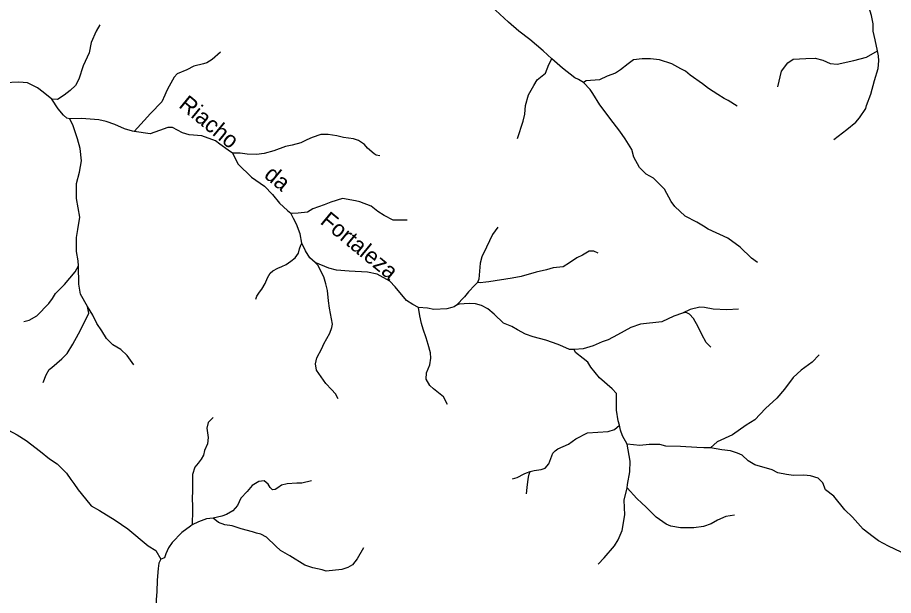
# Model space of a CAD drawing. Extents: x 717.8 to 772.7, y 8672.2 to 8728.
# Drawn here: x 745.36 to 756.1, y 8714.76 to 8721.84 of the extents above; entities that cross this region are included whole.
import ezdxf
from ezdxf.enums import TextEntityAlignment as Align

# ---------------------------------------------------------------- set-up
doc = ezdxf.new("R2010")
doc.units = 0
doc.header["$LTSCALE"] = 0.08
doc.linetypes.add('LONG_DASHED', pattern=[7.5, 6, -1.5])
doc.layers.add('61', color=7, linetype='Continuous')
doc.layers.add('9', color=7, linetype='LONG_DASHED', lineweight=25)

msp = doc.modelspace()

# ---------------------------------------------------------------- linework, layer by layer
at = {"layer": '9'}
for points in [[(755.9085, 8721.4291), (755.8808, 8721.562), (755.8533, 8721.6662), (755.8538, 8721.7586), (755.8357, 8721.8593), (755.7991, 8721.9783), (755.7491, 8722.101), (755.7315, 8722.1641), (755.7427, 8722.3001), (755.7579, 8722.4088), (755.7283, 8722.5079), (755.6979, 8722.5487), (755.5864, 8722.7074), (755.5532, 8722.7782), (755.5344, 8722.8464), (755.5216, 8722.9368), (755.4944, 8723.0723), (755.4579, 8723.2047)], [(751.9137, 8721.3301), (751.808, 8721.4281), (751.6443, 8721.5671), (751.5113, 8721.6684), (751.3817, 8721.7804), (751.225, 8721.9241), (751.0848, 8722.0219), (750.9435, 8722.1126), (750.7822, 8722.2316), (750.6232, 8722.3565), (750.5133, 8722.4849), (750.4066, 8722.5769), (750.2794, 8722.6594), (750.184, 8722.7301), (750.1089, 8722.8014), (750.0747, 8722.8912)], [(746.3739, 8721.7468), (746.3261, 8721.67), (746.2672, 8721.5297), (746.2422, 8721.4041), (746.1689, 8721.245), (746.1149, 8721.0784), (746.0737, 8721.0018), (746.0107, 8720.9418), (745.9353, 8720.8844), (745.8548, 8720.8318), (745.786, 8720.8349)], [(747.8527, 8721.4099), (747.7506, 8721.3199), (747.6842, 8721.2801), (747.6444, 8721.267), (747.5234, 8721.2411), (747.4386, 8721.1941), (747.3222, 8721.1439), (747.2833, 8721.105), (747.2223, 8720.994), (747.1945, 8720.9398), (747.1682, 8720.8843), (747.1332, 8720.8034), (746.9938, 8720.6578), (746.9173, 8720.5734), (746.7951, 8720.4393)], [(751.4954, 8720.3528), (751.5622, 8720.5678), (751.5825, 8720.653), (751.5932, 8720.7586), (751.627, 8720.8904), (751.6927, 8721.0019), (751.7345, 8721.0705), (751.8391, 8721.1526), (751.876, 8721.2582), (751.9137, 8721.3301)], [(752.3013, 8721.0406), (752.2419, 8721.0778), (752.1983, 8721.0955), (752.0444, 8721.2137), (751.9137, 8721.3301)], [(754.188, 8720.7486), (754.0786, 8720.8193), (754.0272, 8720.8426), (753.9508, 8720.8939), (753.8375, 8720.9646), (753.7639, 8721.0237), (753.6109, 8721.1312), (753.5538, 8721.1767), (753.4985, 8721.2076), (753.3848, 8721.2692), (753.2338, 8721.3154), (753.1259, 8721.3278), (753.0223, 8721.3278), (752.9158, 8721.3191), (752.8494, 8721.2692), (752.7578, 8721.1959), (752.6951, 8721.1535), (752.5924, 8721.1175), (752.4995, 8721.0739), (752.3339, 8721.0604), (752.3013, 8721.0406)], [(754.6847, 8720.9864), (754.7326, 8721.1767), (754.8094, 8721.2798), (754.875, 8721.3268), (755.0283, 8721.335), (755.1445, 8721.3358), (755.2364, 8721.3142), (755.3275, 8721.2734), (755.4147, 8721.2654), (755.6157, 8721.3097), (755.7737, 8721.3494), (755.9085, 8721.4291)], [(755.3726, 8720.3404), (755.5333, 8720.4635), (755.6436, 8720.5523), (755.6859, 8720.6067), (755.7644, 8720.721), (755.7731, 8720.757), (755.8258, 8720.8981), (755.8717, 8721.0629), (755.9159, 8721.2127), (755.9255, 8721.3062), (755.9183, 8721.3654), (755.9085, 8721.4291)], [(745.786, 8720.8349), (745.6798, 8720.921), (745.6068, 8720.9741), (745.4873, 8721.0337), (745.378, 8721.0433), (745.2056, 8721.0367), (744.9921, 8721.0126)], [(754.4366, 8718.8354), (754.364, 8718.8886), (754.2255, 8719.0204), (754.0725, 8719.1327), (753.8333, 8719.243), (753.7743, 8719.2789), (753.6929, 8719.3292), (753.5487, 8719.4038), (753.4247, 8719.521), (753.3768, 8719.5838), (753.2972, 8719.7335), (753.1615, 8719.8656), (753.0733, 8719.9179), (752.9881, 8719.9974), (752.9194, 8720.1253), (752.8942, 8720.2192), (752.8143, 8720.3488), (752.7499, 8720.442), (752.6657, 8720.5495), (752.5034, 8720.7669), (752.4191, 8720.9064), (752.3852, 8720.9519), (752.3013, 8721.0406)], [(746.0066, 8720.593), (745.9673, 8720.6038), (745.9263, 8720.6411), (745.8622, 8720.7165), (745.786, 8720.8349)], [(746.7951, 8720.4393), (746.7749, 8720.4438), (746.6756, 8720.4733), (746.5559, 8720.5233), (746.4489, 8720.5603), (746.3601, 8720.5822), (746.1486, 8720.5984), (746.0066, 8720.593)], [(746.1108, 8718.7957), (746.1079, 8718.8541), (746.0858, 8718.9713), (746.0858, 8719.1406), (746.1025, 8719.2378), (746.1261, 8719.3919), (746.0886, 8719.6183), (746.0872, 8719.8029), (746.1233, 8719.9431), (746.1482, 8720.0809), (746.1308, 8720.2321), (746.0994, 8720.3481), (746.0477, 8720.5068), (746.0066, 8720.593)], [(747.9985, 8720.172), (747.945, 8720.2101), (747.8431, 8720.2858), (747.7892, 8720.3238), (747.6239, 8720.3846), (747.467, 8720.3967), (747.3869, 8720.4241), (747.2657, 8720.4876), (747.2075, 8720.4862), (747.1036, 8720.4533), (746.9886, 8720.4087), (746.7951, 8720.4393)], [(749.8056, 8720.1427), (749.7619, 8720.1503), (749.7355, 8720.1649), (749.6557, 8720.2343), (749.6162, 8720.2801), (749.5434, 8720.3294), (749.4844, 8720.3489), (749.3595, 8720.3662), (749.2797, 8720.385), (749.1736, 8720.4016), (749.0813, 8720.4016), (748.9745, 8720.3642), (748.9106, 8720.3378), (748.8357, 8720.301), (748.7311, 8720.2698), (748.6499, 8720.2545), (748.5063, 8720.2032), (748.3876, 8720.1678), (748.294, 8720.1574), (748.1788, 8720.1629), (748.0945, 8720.175), (747.9985, 8720.172)], [(747.9985, 8720.172), (748.0671, 8720.0411), (748.2316, 8719.8809), (748.3903, 8719.7683), (748.4914, 8719.6663), (748.5738, 8719.561), (748.6753, 8719.4714), (748.7162, 8719.4383)], [(750.1409, 8719.3518), (750.0769, 8719.3518), (749.9701, 8719.3518), (749.8583, 8719.4101), (749.7823, 8719.4587), (749.6997, 8719.5235), (749.562, 8719.5787), (749.5078, 8719.5899), (749.3495, 8719.6184), (749.2033, 8719.5721), (749.1236, 8719.539), (748.9841, 8719.4927), (748.9177, 8719.4529), (748.8047, 8719.4397), (748.7383, 8719.4331), (748.7162, 8719.4383)], [(748.8507, 8719.0731), (748.829, 8719.1866), (748.7845, 8719.3037), (748.7494, 8719.3716), (748.7162, 8719.4383)], [(751.2509, 8719.2662), (751.1893, 8719.1761), (751.1124, 8719.0221), (751.0572, 8718.9039), (751.0378, 8718.8245), (751.0213, 8718.6298), (751.0015, 8718.5909)], [(748.2853, 8718.3868), (748.2993, 8718.4207), (748.3297, 8718.4702), (748.3577, 8718.5077), (748.4018, 8718.5772), (748.4276, 8718.6459), (748.4593, 8718.7058), (748.4942, 8718.7337), (748.5554, 8718.7667), (748.6051, 8718.7863), (748.6588, 8718.8121), (748.7163, 8718.851), (748.7665, 8718.8927), (748.8091, 8718.9497), (748.8222, 8719.0017), (748.8362, 8719.0462), (748.8507, 8719.0731)], [(749.0137, 8718.8356), (748.9476, 8718.8935), (748.895, 8718.9778), (748.8507, 8719.0731)], [(752.4814, 8718.9481), (752.4302, 8718.9725), (752.373, 8718.9725), (752.2913, 8718.9233), (752.221, 8718.8929), (752.1319, 8718.8299), (752.0535, 8718.7834), (751.9312, 8718.7677), (751.8486, 8718.746), (751.7218, 8718.7173), (751.5382, 8718.6611), (751.4276, 8718.6407), (751.1409, 8718.5996), (751.104, 8718.5955), (751.0364, 8718.5859), (751.0015, 8718.5909)], [(745.4398, 8718.1114), (745.5057, 8718.1284), (745.5998, 8718.1827), (745.7455, 8718.3322), (745.7934, 8718.3928), (745.8305, 8718.4553), (745.9399, 8718.5645), (746.0695, 8718.7184), (746.1108, 8718.7957)], [(746.2232, 8718.2939), (746.1362, 8718.4463), (746.1163, 8718.5702), (746.1108, 8718.7957)], [(750.2804, 8718.2834), (750.2123, 8718.3216), (750.1316, 8718.3703), (749.992, 8718.5384), (749.928, 8718.6078), (749.7748, 8718.691), (749.6534, 8718.7151), (749.4279, 8718.7293), (749.2737, 8718.7425), (749.1817, 8718.7666), (749.0137, 8718.8356)], [(749.2967, 8717.1665), (749.2605, 8717.2261), (749.2153, 8717.2803), (749.1457, 8717.3542), (749.0307, 8717.5153), (749.0154, 8717.592), (749.0331, 8717.6679), (749.0928, 8717.7805), (749.1193, 8717.8401), (749.1926, 8717.9696), (749.2187, 8718.0388), (749.2244, 8718.078), (749.1894, 8718.2739), (749.1752, 8718.367), (749.165, 8718.49), (749.1434, 8718.575), (749.1205, 8718.6571), (749.0439, 8718.8016), (749.0137, 8718.8356)], [(751.0015, 8718.5909), (750.9688, 8718.5587), (750.8951, 8718.4769), (750.846, 8718.4155), (750.7458, 8718.3102)], [(752.1871, 8717.7691), (752.131, 8717.7697), (752.0482, 8717.806), (751.9918, 8717.8304), (751.8423, 8717.8818), (751.6845, 8717.9249), (751.5936, 8717.9586), (751.4926, 8718.0088), (751.4225, 8718.0493), (751.3236, 8718.0934), (751.2084, 8718.2028), (751.1298, 8718.2651), (751.0505, 8718.3094), (750.9799, 8718.3297), (750.8994, 8718.3318), (750.7791, 8718.3226), (750.7458, 8718.3102)], [(745.6776, 8717.3666), (745.7131, 8717.4598), (745.7535, 8717.5222), (745.7825, 8717.5475), (745.9064, 8717.6534), (745.9723, 8717.7209), (746.0438, 8717.8361), (746.11, 8717.9619), (746.1823, 8718.097), (746.2383, 8718.2128), (746.2232, 8718.2939)], [(746.79, 8717.5802), (746.7077, 8717.6935), (746.6299, 8717.7686), (746.5305, 8717.8265), (746.4536, 8717.9052), (746.3975, 8717.9975), (746.336, 8718.0861), (746.289, 8718.1893), (746.2232, 8718.2939)], [(750.7458, 8718.3102), (750.7191, 8718.2922), (750.6906, 8718.2837), (750.6269, 8718.2674), (750.4682, 8718.2589), (750.3898, 8718.2767), (750.2804, 8718.2834)], [(750.6362, 8717.0943), (750.5863, 8717.1875), (750.5242, 8717.2396), (750.4642, 8717.286), (750.4209, 8717.3271), (750.374, 8717.404), (750.3792, 8717.4845), (750.4195, 8717.5817), (750.4317, 8717.6613), (750.4282, 8717.7261), (750.3975, 8717.8315), (750.3736, 8717.9117), (750.3353, 8718.0182), (750.3174, 8718.0888), (750.2959, 8718.1833), (750.2804, 8718.2834)], [(753.5188, 8718.2138), (753.4118, 8718.1788), (753.2629, 8718.1076), (753.0016, 8718.0793), (752.8816, 8718.0375), (752.7186, 8717.9478), (752.6048, 8717.8857), (752.5308, 8717.8616), (752.42, 8717.8153), (752.2983, 8717.7789), (752.1871, 8717.7691)], [(754.204, 8718.2612), (754.0623, 8718.2564), (753.8943, 8718.2618), (753.7855, 8718.2845), (753.7275, 8718.2869), (753.611, 8718.2601), (753.5188, 8718.2138)], [(753.8644, 8717.7958), (753.8058, 8717.855), (753.752, 8717.9525), (753.7107, 8718.0476), (753.6509, 8718.1487), (753.6044, 8718.202), (753.5607, 8718.2211), (753.5188, 8718.2138)], [(752.7465, 8716.8415), (752.73, 8716.8963), (752.7072, 8717.0242), (752.7072, 8717.2307), (752.6546, 8717.2888), (752.5007, 8717.4212), (752.3941, 8717.5521), (752.3542, 8717.6142), (752.2997, 8717.6574), (752.2038, 8717.733), (752.1871, 8717.7691)], [(755.1933, 8717.703), (755.1054, 8717.6121), (754.9722, 8717.5149), (754.8728, 8717.4247), (754.7667, 8717.2815), (754.6737, 8717.1731), (754.5354, 8717.0482), (754.4033, 8716.906), (754.2983, 8716.8402), (754.1303, 8716.725), (753.9413, 8716.636), (753.8584, 8716.5636)], [(744.1616, 8717.603), (744.2198, 8717.5565), (744.2917, 8717.4651), (744.3624, 8717.3832), (744.4796, 8717.2788), (744.5387, 8717.2308), (744.6779, 8717.1473), (744.857, 8717.0438), (744.9979, 8716.9551), (745.0768, 8716.8943), (745.1826, 8716.8163), (745.3575, 8716.7227), (745.4678, 8716.655), (745.6447, 8716.5179)], [(747.7635, 8716.9376), (747.7002, 8716.8745), (747.6862, 8716.8043), (747.7003, 8716.6921), (747.6933, 8716.615), (747.6582, 8716.5309), (747.6442, 8716.4748), (747.6161, 8716.4258), (747.5801, 8716.3757), (747.5364, 8716.3263), (747.5089, 8716.2397), (747.5105, 8716.0559), (747.5062, 8715.9273), (747.5081, 8715.8649), (747.5108, 8715.8016), (747.5043, 8715.6204)], [(751.6477, 8716.275), (751.6993, 8716.2861), (751.7829, 8716.2997), (751.8337, 8716.3145), (751.878, 8716.369), (751.9266, 8716.4988), (751.9543, 8716.5285), (751.99, 8716.5521), (752.1181, 8716.6098), (752.2105, 8716.6746), (752.3541, 8716.7487), (752.4785, 8716.758), (752.6045, 8716.7649), (752.6834, 8716.7871), (752.7465, 8716.8415)], [(752.8381, 8716.6095), (752.7833, 8716.7129), (752.7556, 8716.781), (752.7465, 8716.8415)], [(753.8584, 8716.5636), (753.7796, 8716.5646), (753.6947, 8716.5672), (753.4906, 8716.579), (753.3143, 8716.5842), (753.2397, 8716.6034), (753.1076, 8716.6034), (752.9952, 8716.592), (752.8381, 8716.6095)], [(752.8382, 8716.0751), (752.8431, 8716.1137), (752.8699, 8716.272), (752.8748, 8716.4011), (752.8381, 8716.6095)], [(745.6447, 8716.5179), (745.7562, 8716.4314), (745.8495, 8716.3671), (745.8928, 8716.3247), (745.9628, 8716.2521), (746.0188, 8716.1772), (746.0543, 8716.1262), (746.1087, 8716.0482), (746.1426, 8716.0056)], [(756.1993, 8715.2883), (756.0421, 8715.3587), (755.9212, 8715.4256), (755.8554, 8715.4761), (755.7334, 8715.5689), (755.6007, 8715.7147), (755.5068, 8715.804), (755.3706, 8715.9742), (755.2697, 8716.0482), (755.238, 8716.1339), (755.18, 8716.1939), (755.0843, 8716.2231), (755.0045, 8716.2305), (754.8789, 8716.2243), (754.792, 8716.2395), (754.684, 8716.2583), (754.6148, 8716.2936), (754.4055, 8716.3555), (754.3627, 8716.3813), (754.324, 8716.4053), (754.25, 8716.4752), (754.1926, 8716.4989), (754.1039, 8716.5296), (753.9989, 8716.5415), (753.8584, 8716.5636)], [(751.4335, 8716.1842), (751.4908, 8716.1991), (751.5751, 8716.2443), (751.6055, 8716.2585), (751.6477, 8716.275)], [(751.6036, 8716.0014), (751.6143, 8716.0791), (751.6188, 8716.147), (751.6282, 8716.2032), (751.6375, 8716.243), (751.6477, 8716.275)], [(748.9662, 8716.1593), (748.8505, 8716.1302), (748.7898, 8716.1326), (748.6716, 8716.1237), (748.5987, 8716.1067), (748.5534, 8716.0735), (748.521, 8716.0524), (748.4886, 8716.0516), (748.4602, 8716.0791), (748.4351, 8716.1212), (748.3874, 8716.1593), (748.3218, 8716.1528), (748.2392, 8716.1026), (748.1785, 8716.0306), (748.1032, 8715.948), (748.0592, 8715.8564), (748.003, 8715.7933), (747.9273, 8715.7483), (747.8694, 8715.7257), (747.764, 8715.7021)], [(752.4838, 8715.1377), (752.5576, 8715.2156), (752.6824, 8715.363), (752.7261, 8715.4363), (752.7763, 8715.5506), (752.8109, 8715.7423), (752.8026, 8715.9235), (752.8382, 8716.0751)], [(754.1551, 8715.7411), (754.0472, 8715.7219), (753.9472, 8715.679), (753.8674, 8715.6332), (753.7762, 8715.5999), (753.655, 8715.5851), (753.4905, 8715.5842), (753.3739, 8715.6039), (753.3181, 8715.6285), (753.1939, 8715.7132), (753.0669, 8715.8423), (753.0201, 8715.885), (752.9577, 8715.9433), (752.8382, 8716.0751)], [(746.1426, 8716.0056), (746.2657, 8715.8525), (746.3671, 8715.7976), (746.5616, 8715.6803), (746.7142, 8715.5723), (746.9673, 8715.3638), (747.0585, 8715.3079), (747.1227, 8715.2001)], [(747.764, 8715.7021), (747.6806, 8715.6959), (747.5813, 8715.6598), (747.5043, 8715.6204)], [(749.6073, 8715.3381), (749.5287, 8715.2053), (749.4727, 8715.1302), (749.414, 8715.0976), (749.3387, 8715.0721), (749.1475, 8715.0542), (749.0978, 8715.0696), (748.9848, 8715.0949), (748.8861, 8715.1283), (748.7027, 8715.2431), (748.5879, 8715.3064), (748.5319, 8715.3606), (748.4172, 8715.4691), (748.3476, 8715.5052), (748.2932, 8715.5187), (748.2453, 8715.5368), (748.1044, 8715.5739), (747.9959, 8715.6073), (747.9056, 8715.6227), (747.8279, 8715.6498), (747.764, 8715.7021)], [(747.5043, 8715.6204), (747.4829, 8715.6038), (747.3774, 8715.5266), (747.2613, 8715.4057), (747.2139, 8715.3386), (747.1841, 8715.2642), (747.1637, 8715.2186), (747.1227, 8715.2001)], [(747.1227, 8715.2001), (747.0982, 8715.1509), (747.0864, 8715.0854), (747.0752, 8714.9446), (747.0724, 8714.7996), (747.0649, 8714.7083), (747.0612, 8714.5771), (747.05, 8714.3099), (747.0537, 8714.1973), (747.0361, 8714.0204), (747.0232, 8713.9746)]]:
    msp.add_lwpolyline(points, dxfattribs=at)

# ---------------------------------------------------------------- texts
at = {"layer": '61'}
msp.add_text('Riacho       da        Fortaleza', height=0.2, rotation=320.576, dxfattribs=at).set_placement((748.6267, 8719.678), align=Align.CENTER)

doc.saveas('drawing.dxf')
